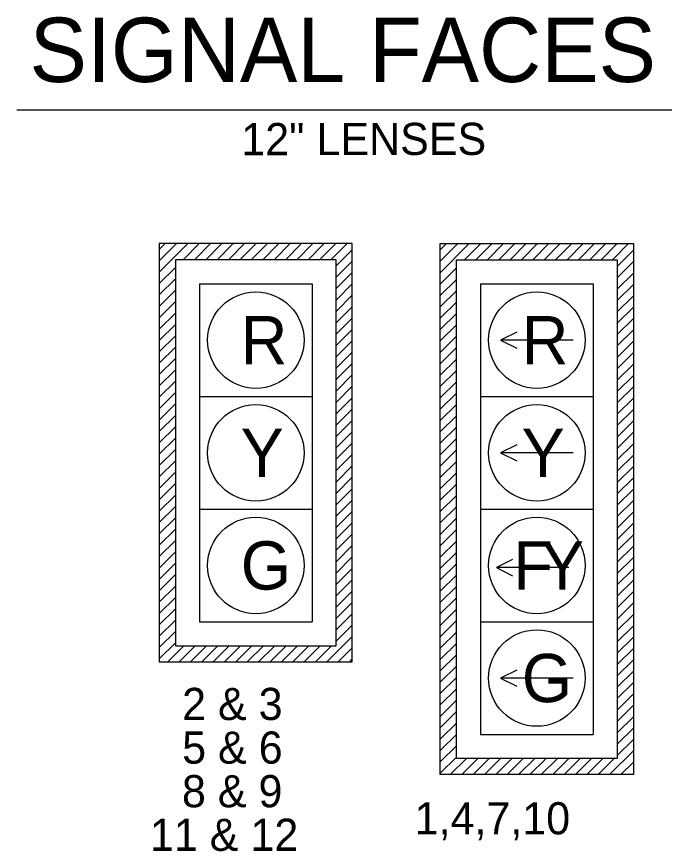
# Model space of a CAD drawing. Extents: x 1 to 35.4, y 0.4 to 10.6.
# Drawn here: x 3.561 to 4.903, y 8.649 to 10.378 of the extents above; entities that cross this region are included whole.
import ezdxf

# ---------------------------------------------------------------- set-up
doc = ezdxf.new("R2010")
doc.units = 0
doc.layers.add('T_Drafting', color=7, linetype='Continuous')
doc.layers.add('T_Notes', color=7, linetype='Continuous')

msp = doc.modelspace()

# ---------------------------------------------------------------- linework, layer by layer
at = {"layer": 'T_Drafting'}
for p, q in [((4.2563, 9.9082), (3.8563, 9.9082)), ((3.8563, 9.9082), (3.8563, 9.0415)), ((3.8563, 9.849), (3.9154, 9.9082)), ((3.8563, 9.8726), (3.8918, 9.9082)), ((3.8563, 9.8962), (3.8682, 9.9082)), ((3.9056, 9.8748), (3.9389, 9.9082)), ((3.9292, 9.8748), (3.9625, 9.9082)), ((3.9528, 9.8748), (3.9861, 9.9082)), ((3.9763, 9.8748), (4.0097, 9.9082)), ((3.9999, 9.8748), (4.0332, 9.9082)), ((4.0235, 9.8748), (4.0568, 9.9082)), ((4.047, 9.8748), (4.0804, 9.9082)), ((4.0706, 9.8748), (4.1039, 9.9082)), ((4.0942, 9.8748), (4.1275, 9.9082)), ((4.1177, 9.8748), (4.1511, 9.9082)), ((4.1413, 9.8748), (4.1747, 9.9082)), ((4.1649, 9.8748), (4.1982, 9.9082)), ((4.1885, 9.8748), (4.2218, 9.9082)), ((4.212, 9.8748), (4.2454, 9.9082)), ((4.2229, 9.8622), (4.2563, 9.8955)), ((4.2563, 9.0415), (4.2563, 9.9082)), ((4.4386, 8.8082), (4.4386, 9.9082)), ((4.4386, 9.9082), (4.8386, 9.9082)), ((4.4386, 9.848), (4.4987, 9.9082)), ((4.4386, 9.8716), (4.4751, 9.9082)), ((4.4386, 9.8952), (4.4515, 9.9082)), ((4.4889, 9.8748), (4.5223, 9.9082)), ((4.5125, 9.8748), (4.5458, 9.9082)), ((4.5361, 9.8748), (4.5694, 9.9082)), ((4.5596, 9.8748), (4.593, 9.9082)), ((4.5832, 9.8748), (4.6165, 9.9082)), ((4.6068, 9.8748), (4.6401, 9.9082)), ((4.6303, 9.8748), (4.6637, 9.9082)), ((4.6539, 9.8748), (4.6872, 9.9082)), ((4.6775, 9.8748), (4.7108, 9.9082)), ((4.7011, 9.8748), (4.7344, 9.9082)), ((4.7246, 9.8748), (4.758, 9.9082)), ((4.7482, 9.8748), (4.7815, 9.9082)), ((4.7718, 9.8748), (4.8051, 9.9082)), ((4.7953, 9.8748), (4.8287, 9.9082)), ((4.8052, 9.8612), (4.8386, 9.8945)), ((4.8386, 9.9082), (4.8386, 8.8082)), ((3.8563, 9.8255), (3.8896, 9.8588)), ((4.2229, 9.8386), (4.2563, 9.8719)), ((4.4386, 9.8245), (4.4719, 9.8578)), ((4.8052, 9.8376), (4.8386, 9.8709)), ((4.2229, 9.815), (4.2563, 9.8484)), ((4.8052, 9.814), (4.8386, 9.8473)), ((3.8563, 9.8019), (3.8896, 9.8352)), ((3.9396, 9.8248), (4.1729, 9.8248)), ((3.9396, 9.8248), (3.9396, 9.5915)), ((4.1729, 9.8248), (4.1729, 9.5915)), ((4.2229, 9.7914), (4.2563, 9.8248)), ((4.4386, 9.8009), (4.4719, 9.8342)), ((4.5219, 9.8248), (4.7552, 9.8248)), ((4.5219, 9.8248), (4.5219, 9.5915)), ((4.7552, 9.8248), (4.7552, 9.5915)), ((4.8052, 9.7904), (4.8386, 9.8238)), ((3.8563, 9.7783), (3.8896, 9.8117)), ((4.4386, 9.7773), (4.4719, 9.8107)), ((3.8563, 9.7548), (3.8896, 9.7881)), ((4.2229, 9.7679), (4.2563, 9.8012)), ((4.8052, 9.7669), (4.8386, 9.8002)), ((4.2229, 9.7443), (4.2563, 9.7776)), ((4.4386, 9.7538), (4.4719, 9.7871)), ((4.8052, 9.7433), (4.8386, 9.7766)), ((3.8563, 9.7312), (3.8896, 9.7645)), ((4.2229, 9.7207), (4.2563, 9.7541)), ((4.4386, 9.7302), (4.4719, 9.7635)), ((4.8052, 9.7197), (4.8386, 9.7531)), ((3.8563, 9.7076), (3.8896, 9.741)), ((4.4386, 9.7066), (4.4719, 9.74)), ((4.2229, 9.6972), (4.2563, 9.7305)), ((4.8052, 9.6962), (4.8386, 9.7295)), ((3.8563, 9.6841), (3.8896, 9.7174)), ((4.2229, 9.6736), (4.2563, 9.7069)), ((4.4386, 9.683), (4.4719, 9.7164)), ((4.7136, 9.7082), (4.5636, 9.7082)), ((4.8052, 9.6726), (4.8386, 9.7059)), ((3.8563, 9.6605), (3.8896, 9.6938)), ((4.4386, 9.6595), (4.4719, 9.6928)), ((3.8563, 9.6369), (3.8896, 9.6702)), ((4.2229, 9.65), (4.2563, 9.6834)), ((4.4386, 9.6359), (4.4719, 9.6692)), ((4.8052, 9.649), (4.8386, 9.6824)), ((4.2229, 9.6265), (4.2563, 9.6598)), ((4.8052, 9.6255), (4.8386, 9.6588)), ((3.8563, 9.6133), (3.8896, 9.6467)), ((4.2229, 9.6029), (4.2563, 9.6362)), ((4.4386, 9.6123), (4.4719, 9.6457)), ((4.8052, 9.6019), (4.8386, 9.6352)), ((3.8563, 9.5898), (3.8896, 9.6231)), ((4.4386, 9.5888), (4.4719, 9.6221)), ((3.8563, 9.5662), (3.8896, 9.5995)), ((4.2229, 9.5793), (4.2563, 9.6127)), ((4.4386, 9.5652), (4.4719, 9.5985)), ((4.8052, 9.5783), (4.8386, 9.6116)), ((3.9396, 9.5915), (4.1729, 9.5915)), ((3.9396, 9.5915), (3.9396, 9.3582)), ((4.1729, 9.5915), (4.1729, 9.3582)), ((4.2229, 9.5557), (4.2563, 9.5891)), ((4.5219, 9.5915), (4.7552, 9.5915)), ((4.5219, 9.5915), (4.5219, 9.3582)), ((4.7552, 9.5915), (4.7552, 9.3582)), ((4.8052, 9.5547), (4.8386, 9.5881)), ((3.8563, 9.5426), (3.8896, 9.576)), ((4.2229, 9.5322), (4.2563, 9.5655)), ((4.4386, 9.5416), (4.4719, 9.575)), ((4.8052, 9.5312), (4.8386, 9.5645)), ((3.8563, 9.5191), (3.8896, 9.5524)), ((4.4386, 9.5181), (4.4719, 9.5514)), ((3.8563, 9.4955), (3.8896, 9.5288)), ((4.2229, 9.5086), (4.2563, 9.5419)), ((4.8052, 9.5076), (4.8386, 9.5409)), ((4.2229, 9.485), (4.2563, 9.5184)), ((4.4386, 9.4945), (4.4719, 9.5278)), ((4.8052, 9.484), (4.8386, 9.5174)), ((3.8563, 9.4719), (3.8896, 9.5053)), ((4.2229, 9.4615), (4.2563, 9.4948)), ((4.4386, 9.4709), (4.4719, 9.5043)), ((4.8052, 9.4605), (4.8386, 9.4938)), ((3.8563, 9.4484), (3.8896, 9.4817)), ((4.4386, 9.4473), (4.4719, 9.4807)), ((4.2229, 9.4379), (4.2563, 9.4712)), ((4.7136, 9.4748), (4.5636, 9.4748)), ((4.8052, 9.4369), (4.8386, 9.4702)), ((3.8563, 9.4248), (3.8896, 9.4581)), ((4.2229, 9.4143), (4.2563, 9.4477)), ((4.4386, 9.4238), (4.4719, 9.4571)), ((4.8052, 9.4133), (4.8386, 9.4467)), ((3.8563, 9.4012), (3.8896, 9.4345)), ((4.2229, 9.3908), (4.2563, 9.4241)), ((4.4386, 9.4002), (4.4719, 9.4335)), ((3.8563, 9.3776), (3.8896, 9.411)), ((4.4386, 9.3766), (4.4719, 9.41)), ((4.8052, 9.3898), (4.8386, 9.4231)), ((4.2229, 9.3672), (4.2563, 9.4005)), ((4.8052, 9.3662), (4.8386, 9.3995)), ((3.8563, 9.3541), (3.8896, 9.3874)), ((4.2229, 9.3436), (4.2563, 9.3769)), ((4.4386, 9.3531), (4.4719, 9.3864)), ((4.8052, 9.3426), (4.8386, 9.3759)), ((3.8563, 9.3305), (3.8896, 9.3638)), ((3.9396, 9.3582), (4.1729, 9.3582)), ((3.9396, 9.3582), (3.9396, 9.1248)), ((4.1729, 9.3582), (4.1729, 9.1248)), ((4.4386, 9.3295), (4.4719, 9.3628)), ((4.5219, 9.3582), (4.7552, 9.3582)), ((4.5219, 9.3582), (4.5219, 9.1248)), ((4.7552, 9.3582), (4.7552, 9.1248)), ((3.8563, 9.3069), (3.8896, 9.3403)), ((4.2229, 9.32), (4.2563, 9.3534)), ((4.4386, 9.3059), (4.4719, 9.3393)), ((4.8052, 9.319), (4.8386, 9.3524)), ((4.2229, 9.2965), (4.2563, 9.3298)), ((4.8052, 9.2955), (4.8386, 9.3288)), ((3.8563, 9.2834), (3.8896, 9.3167)), ((4.2229, 9.2729), (4.2563, 9.3062)), ((4.4386, 9.2824), (4.4719, 9.3157)), ((4.8052, 9.2719), (4.8386, 9.3052)), ((3.8563, 9.2598), (3.8896, 9.2931)), ((4.4386, 9.2588), (4.4719, 9.2921)), ((3.8563, 9.2362), (3.8896, 9.2696)), ((4.2229, 9.2493), (4.2563, 9.2827)), ((4.4386, 9.2352), (4.4719, 9.2685)), ((4.8052, 9.2483), (4.8386, 9.2817)), ((4.2229, 9.2258), (4.2563, 9.2591)), ((4.8052, 9.2248), (4.8386, 9.2581)), ((3.8563, 9.2127), (3.8896, 9.246)), ((4.2229, 9.2022), (4.2563, 9.2355)), ((4.4386, 9.2116), (4.4719, 9.245)), ((4.7048, 9.2369), (4.5548, 9.2369)), ((4.8052, 9.2012), (4.8386, 9.2345)), ((3.8563, 9.1891), (3.8896, 9.2224)), ((4.4386, 9.1881), (4.4719, 9.2214)), ((4.2229, 9.1786), (4.2563, 9.212)), ((4.8052, 9.1776), (4.8386, 9.211)), ((3.8563, 9.1655), (3.8896, 9.1988)), ((4.2229, 9.1551), (4.2563, 9.1884)), ((4.4386, 9.1645), (4.4719, 9.1978)), ((4.8052, 9.154), (4.8386, 9.1874)), ((3.8563, 9.1419), (3.8896, 9.1753)), ((4.2229, 9.1315), (4.2563, 9.1648)), ((4.4386, 9.1409), (4.4719, 9.1743)), ((3.8563, 9.1184), (3.8896, 9.1517)), ((4.4386, 9.1174), (4.4719, 9.1507)), ((4.8052, 9.1305), (4.8386, 9.1638)), ((4.2229, 9.1079), (4.2563, 9.1412)), ((4.8052, 9.1069), (4.8386, 9.1402)), ((3.8563, 9.0948), (3.8896, 9.1281)), ((3.9396, 9.1248), (4.1729, 9.1248)), ((4.2229, 9.0843), (4.2563, 9.1177)), ((4.4386, 9.0938), (4.4719, 9.1271)), ((4.5219, 9.1248), (4.7552, 9.1248)), ((4.5219, 9.1248), (4.5219, 8.8915)), ((4.7552, 9.1248), (4.7552, 8.8915)), ((4.8052, 9.0833), (4.8386, 9.1167)), ((3.8563, 9.0712), (3.8896, 9.1046)), ((4.4386, 9.0702), (4.4719, 9.1036)), ((3.8563, 9.0477), (3.8896, 9.081)), ((4.2037, 9.0415), (4.2563, 9.0941)), ((4.4386, 9.0467), (4.4719, 9.08)), ((4.8052, 9.0598), (4.8386, 9.0931)), ((3.8737, 9.0415), (3.907, 9.0748)), ((3.8972, 9.0415), (3.9306, 9.0748)), ((3.9208, 9.0415), (3.9541, 9.0748)), ((3.9444, 9.0415), (3.9777, 9.0748)), ((3.968, 9.0415), (4.0013, 9.0748)), ((3.9915, 9.0415), (4.0249, 9.0748)), ((4.0151, 9.0415), (4.0484, 9.0748)), ((4.0387, 9.0415), (4.072, 9.0748)), ((4.0622, 9.0415), (4.0956, 9.0748)), ((4.0858, 9.0415), (4.1191, 9.0748)), ((4.1094, 9.0415), (4.1427, 9.0748)), ((4.1329, 9.0415), (4.1663, 9.0748)), ((4.1565, 9.0415), (4.1898, 9.0748)), ((4.1801, 9.0415), (4.2134, 9.0748)), ((4.2272, 9.0415), (4.2563, 9.0705)), ((4.8052, 9.0362), (4.8386, 9.0695)), ((4.2508, 9.0415), (4.2563, 9.047)), ((4.4386, 9.0231), (4.4719, 9.0564)), ((4.8052, 9.0126), (4.8386, 9.046)), ((3.8563, 9.0415), (4.2563, 9.0415)), ((4.4386, 8.9995), (4.4719, 9.0328)), ((4.4386, 8.9759), (4.4719, 9.0093)), ((4.8052, 8.9891), (4.8386, 9.0224)), ((4.7136, 9.0082), (4.5636, 9.0082)), ((4.8052, 8.9655), (4.8386, 8.9988)), ((4.4386, 8.9524), (4.4719, 8.9857)), ((4.8052, 8.9419), (4.8386, 8.9752)), ((4.4386, 8.9288), (4.4719, 8.9621)), ((4.8052, 8.9183), (4.8386, 8.9517)), ((4.4386, 8.9052), (4.4719, 8.9386)), ((4.8052, 8.8948), (4.8386, 8.9281)), ((4.4386, 8.8817), (4.4719, 8.915)), ((4.4386, 8.8581), (4.4719, 8.8914)), ((4.5219, 8.8915), (4.7552, 8.8915)), ((4.8052, 8.8712), (4.8386, 8.9045)), ((4.8052, 8.8476), (4.8386, 8.881)), ((4.4386, 8.8345), (4.4719, 8.8679)), ((4.7893, 8.8082), (4.8386, 8.8574)), ((4.4386, 8.811), (4.4719, 8.8443)), ((4.4593, 8.8082), (4.4927, 8.8415)), ((4.4829, 8.8082), (4.5162, 8.8415)), ((4.5065, 8.8082), (4.5398, 8.8415)), ((4.5301, 8.8082), (4.5634, 8.8415)), ((4.5536, 8.8082), (4.587, 8.8415)), ((4.5772, 8.8082), (4.6105, 8.8415)), ((4.6008, 8.8082), (4.6341, 8.8415)), ((4.6243, 8.8082), (4.6577, 8.8415)), ((4.6479, 8.8082), (4.6812, 8.8415)), ((4.6715, 8.8082), (4.7048, 8.8415)), ((4.695, 8.8082), (4.7284, 8.8415)), ((4.7186, 8.8082), (4.7519, 8.8415)), ((4.7422, 8.8082), (4.7755, 8.8415)), ((4.7658, 8.8082), (4.7991, 8.8415)), ((4.8129, 8.8082), (4.8386, 8.8338)), ((4.8386, 8.8082), (4.4386, 8.8082)), ((4.8365, 8.8082), (4.8386, 8.8103))]:
    msp.add_line(p, q, dxfattribs=at)
for points in [[(4.2229, 9.0748), (4.2229, 9.8748), (3.8896, 9.8748), (3.8896, 9.0748)], [(4.4719, 8.8415), (4.4719, 9.8748), (4.8052, 9.8748), (4.8052, 8.8415)]]:
    msp.add_lwpolyline(points, close=True, dxfattribs=at)
for points in [[(4.5969, 9.7248), (4.5636, 9.7082), (4.5969, 9.6915)], [(4.5969, 9.4915), (4.5636, 9.4748), (4.5969, 9.4582)], [(4.5881, 9.2535), (4.5548, 9.2369), (4.5881, 9.2202)], [(4.5969, 9.0248), (4.5636, 9.0082), (4.5969, 8.9915)]]:
    msp.add_lwpolyline(points, dxfattribs=at)
for centre in [(4.0563, 9.7082), (4.6386, 9.7082), (4.0563, 9.4748), (4.6386, 9.4748), (4.0563, 9.2415), (4.6386, 9.2415), (4.6386, 9.0082)]:
    msp.add_circle(centre, 0.1, dxfattribs=at)
at = {"layer": 'T_Notes'}
msp.add_line((3.5609, 10.1853), (5.1973, 10.1853), dxfattribs=at)

# ---------------------------------------------------------------- texts
at = {"layer": 'T_Drafting'}
msp.add_text('12" LENSES', height=0.06667, rotation=0.072, dxfattribs=at).set_placement((4.0263, 10.0914))
for s, p in [('R', (4.0252, 9.6582)), ('R', (4.6075, 9.6582)), ('Y', (4.0248, 9.4248)), ('Y', (4.6071, 9.4248)), ('G', (4.0252, 9.1915)), ('F', (4.5901, 9.1915)), ('Y', (4.6472, 9.1915)), ('G', (4.6075, 8.9582))]:
    msp.add_text(s, height=0.1, dxfattribs=at).set_placement(p)
at = {"layer": 'T_Notes'}
for s, height, p in [('SIGNAL FACES', 0.133333, (3.5875, 10.2431)), ('2 & 3', 0.06667, (3.9036, 8.9212)), ('5 & 6', 0.06667, (3.9037, 8.8308)), ('8 & 9', 0.06667, (3.9033, 8.7405)), ('1,4,7,10', 0.06667, (4.3854, 8.6843)), ('11 & 12', 0.06667, (3.837, 8.6502))]:
    msp.add_text(s, height=height, dxfattribs=at).set_placement(p)

doc.saveas('drawing.dxf')
